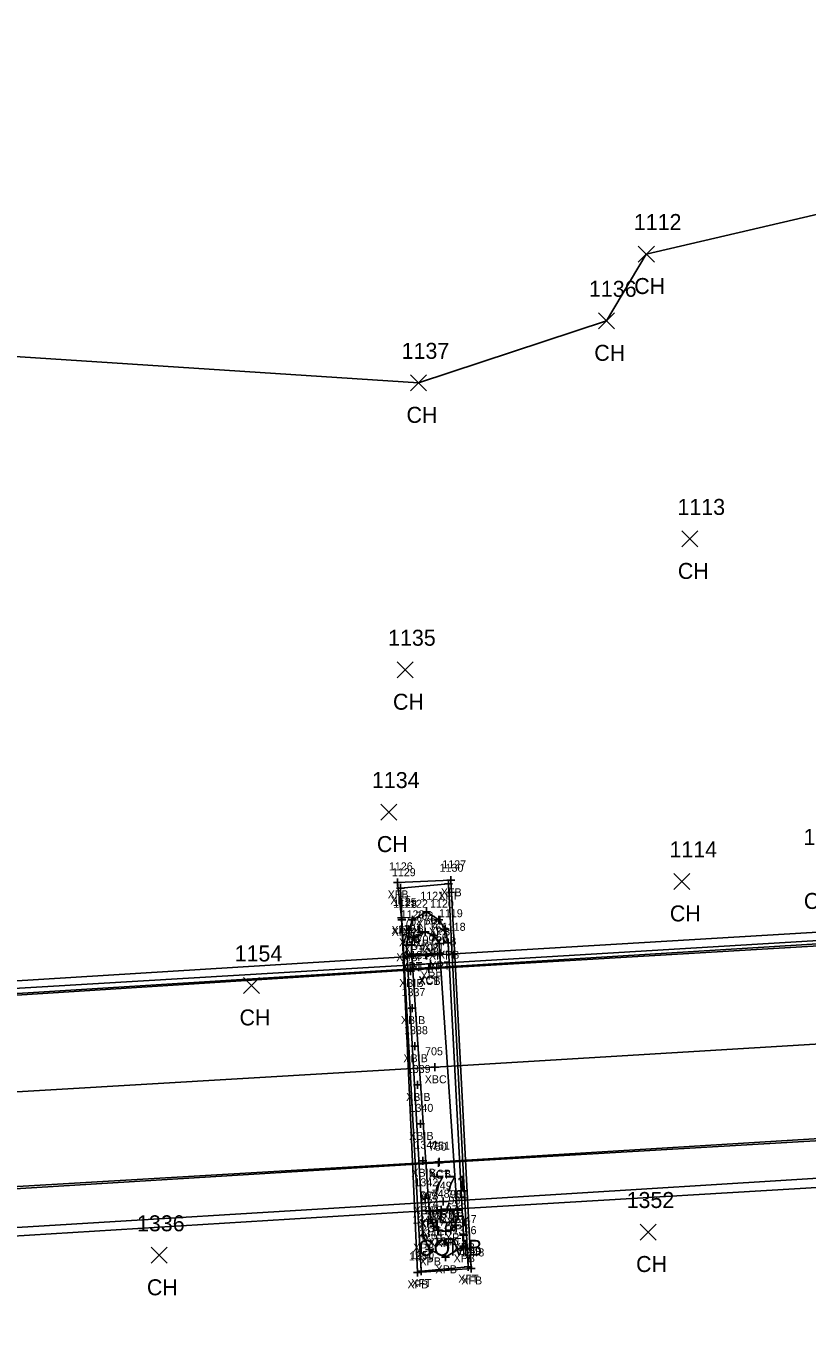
# Model space of a CAD drawing. Extents: x 1716490 to 1717645, y 888034 to 890004.
# Drawn here: x 1717066.5 to 1717164.1, y 888212.7 to 888374.8 of the extents above; entities that cross this region are included whole.
import ezdxf

# ---------------------------------------------------------------- set-up
doc = ezdxf.new("R2010")
doc.units = 0
for name, color, linetype in [('B_A', 7, 'Continuous'), ('B_I', 7, 'Continuous'), ('B_TIC', 7, 'Continuous'), ('BDC', 7, 'Continuous'), ('BELB', 7, 'Continuous'), ('BF', 7, 'Continuous'), ('BFT', 7, 'Continuous'), ('BR', 7, 'Continuous'), ('BSUBM', 7, 'Continuous'), ('L_A', 7, 'Continuous'), ('L_I', 7, 'Continuous'), ('L_TIC', 7, 'Continuous'), ('LSOGP', 7, 'Continuous'), ('U_A', 7, 'Continuous'), ('U_I', 7, 'Continuous'), ('UP', 7, 'Continuous')]:
    doc.layers.add(name, color=color, linetype=linetype)

msp = doc.modelspace()

# ---------------------------------------------------------------- linework, layer by layer
at = {"layer": 'B_TIC'}
for p, q in [((1717119.59, 888268.03), (1717119.67, 888268.03)), ((1717112.95, 888267.77), (1717113.03, 888267.77)), ((1717113.3, 888267.04), (1717113.38, 888267.04)), ((1717119.3, 888267.6), (1717119.37, 888267.6)), ((1717113.42, 888263.33), (1717113.5, 888263.33)), ((1717113.47, 888263.09), (1717113.54, 888263.09)), ((1717114.82, 888263.1), (1717114.9, 888263.1)), ((1717116.56, 888264.1), (1717116.64, 888264.1)), ((1717118.11, 888263.11), (1717118.19, 888263.11)), ((1717114.38, 888261.78), (1717114.46, 888261.78)), ((1717116.38, 888261.61), (1717116.45, 888261.61)), ((1717118.89, 888261.91), (1717118.97, 888261.91)), ((1717114.04, 888259.92), (1717114.12, 888259.92)), ((1717114.67, 888259.96), (1717114.75, 888259.96)), ((1717114.99, 888260.93), (1717115.07, 888260.93)), ((1717117.48, 888261.13), (1717117.56, 888261.13)), ((1717118.14, 888260.13), (1717118.21, 888260.13)), ((1717119.25, 888260.22), (1717119.33, 888260.22)), ((1717114.71, 888258.8), (1717114.78, 888258.8)), ((1717114.72, 888258.65), (1717114.8, 888258.65)), ((1717116.54, 888258.64), (1717116.62, 888258.64)), ((1717118.2, 888258.89), (1717118.28, 888258.89)), ((1717118.23, 888258.88), (1717118.31, 888258.88)), ((1717114.57, 888256.69), (1717114.65, 888256.69)), ((1717116.83, 888257.09), (1717116.91, 888257.09)), ((1717116.83, 888256.95), (1717116.91, 888256.95)), ((1717117.07, 888257.61), (1717117.14, 888257.61)), ((1717114.79, 888252.05), (1717114.86, 888252.05)), ((1717115.1, 888247.29), (1717115.18, 888247.29)), ((1717117.6, 888244.66), (1717117.68, 888244.66)), ((1717115.44, 888242.45), (1717115.52, 888242.45)), ((1717115.83, 888237.59), (1717115.9, 888237.59)), ((1717116.1, 888232.98), (1717116.18, 888232.98)), ((1717118.08, 888232.73), (1717118.15, 888232.73)), ((1717118.15, 888232.86), (1717118.23, 888232.86)), ((1717116.39, 888228.28), (1717116.46, 888228.28)), ((1717118.66, 888227.87), (1717118.73, 888227.87)), ((1717116.88, 888226.66), (1717116.96, 888226.66)), ((1717117, 888226.63), (1717117.08, 888226.63)), ((1717118.39, 888226.86), (1717118.47, 888226.86)), ((1717120.37, 888226.8), (1717120.44, 888226.8)), ((1717120.4, 888226.79), (1717120.48, 888226.79)), ((1717120.53, 888226.03), (1717120.61, 888226.03)), ((1717117.03, 888225.65), (1717117.1, 888225.65)), ((1717117.47, 888224.79), (1717117.54, 888224.79)), ((1717118.07, 888224.3), (1717118.15, 888224.3)), ((1717118.99, 888224.18), (1717119.07, 888224.18)), ((1717119.58, 888224.32), (1717119.66, 888224.32)), ((1717120.15, 888224.9), (1717120.22, 888224.9)), ((1717116.15, 888223.63), (1717116.22, 888223.63)), ((1717121.2, 888223.68), (1717121.28, 888223.68)), ((1717116.95, 888221.9), (1717117.03, 888221.9)), ((1717118.94, 888220.91), (1717119.02, 888220.91)), ((1717121.21, 888222.3), (1717121.28, 888222.3)), ((1717121.78, 888219.73), (1717121.85, 888219.73)), ((1717122.15, 888219.52), (1717122.23, 888219.52)), ((1717115.42, 888219.02), (1717115.5, 888219.02)), ((1717115.91, 888219.18), (1717115.99, 888219.18))]:
    msp.add_line(p, q, dxfattribs=at)
for points in [[(1717112.95, 888267.27), (1717112.95, 888268.27)], [(1717119.09, 888268.03), (1717120.09, 888268.03)], [(1717119.29, 888267.1), (1717119.29, 888268.1)], [(1717119.59, 888267.53), (1717119.59, 888268.53)], [(1717112.45, 888267.77), (1717113.45, 888267.77)], [(1717112.8, 888267.04), (1717113.8, 888267.04)], [(1717113.3, 888266.54), (1717113.3, 888267.54)], [(1717118.79, 888267.6), (1717119.79, 888267.6)], [(1717112.92, 888263.33), (1717113.92, 888263.33)], [(1717112.97, 888263.09), (1717113.97, 888263.09)], [(1717113.42, 888262.83), (1717113.42, 888263.83)], [(1717113.47, 888262.59), (1717113.47, 888263.59)], [(1717114.32, 888263.1), (1717115.32, 888263.1)], [(1717114.82, 888262.6), (1717114.82, 888263.6)], [(1717116.06, 888264.1), (1717117.06, 888264.1)], [(1717116.56, 888263.6), (1717116.56, 888264.6)], [(1717117.61, 888263.11), (1717118.61, 888263.11)], [(1717118.11, 888262.61), (1717118.11, 888263.61)], [(1717113.88, 888261.78), (1717114.88, 888261.78)], [(1717114.38, 888261.28), (1717114.38, 888262.28)], [(1717114.99, 888260.43), (1717114.99, 888261.43)], [(1717115.87, 888261.61), (1717116.87, 888261.61)], [(1717116.37, 888261.11), (1717116.37, 888262.11)], [(1717117.48, 888260.63), (1717117.48, 888261.63)], [(1717118.39, 888261.91), (1717119.39, 888261.91)], [(1717118.89, 888261.41), (1717118.89, 888262.41)], [(1717113.54, 888259.92), (1717114.54, 888259.92)], [(1717114.04, 888259.42), (1717114.04, 888260.42)], [(1717114.17, 888259.96), (1717115.17, 888259.96)], [(1717114.49, 888260.93), (1717115.49, 888260.93)], [(1717114.67, 888259.46), (1717114.67, 888260.46)], [(1717116.98, 888261.13), (1717117.98, 888261.13)], [(1717117.63, 888260.13), (1717118.63, 888260.13)], [(1717118.13, 888259.63), (1717118.13, 888260.63)], [(1717118.75, 888260.22), (1717119.75, 888260.22)], [(1717119.25, 888259.72), (1717119.25, 888260.72)], [(1717114.2, 888258.8), (1717115.2, 888258.8)], [(1717114.22, 888258.65), (1717115.22, 888258.65)], [(1717114.7, 888258.3), (1717114.7, 888259.3)], [(1717114.72, 888258.15), (1717114.72, 888259.15)], [(1717116.04, 888258.64), (1717117.04, 888258.64)], [(1717116.54, 888258.14), (1717116.54, 888259.14)], [(1717117.7, 888258.89), (1717118.7, 888258.89)], [(1717117.73, 888258.88), (1717118.73, 888258.88)], [(1717118.2, 888258.39), (1717118.2, 888259.39)], [(1717118.23, 888258.38), (1717118.23, 888259.38)], [(1717114.07, 888256.69), (1717115.07, 888256.69)], [(1717114.57, 888256.19), (1717114.57, 888257.19)], [(1717116.33, 888257.09), (1717117.33, 888257.09)], [(1717116.33, 888256.95), (1717117.33, 888256.95)], [(1717116.56, 888257.61), (1717117.56, 888257.61)], [(1717116.83, 888256.59), (1717116.83, 888257.59)], [(1717116.83, 888256.45), (1717116.83, 888257.45)], [(1717117.06, 888257.11), (1717117.06, 888258.11)], [(1717114.28, 888252.05), (1717115.28, 888252.05)], [(1717114.78, 888251.55), (1717114.78, 888252.55)], [(1717114.6, 888247.29), (1717115.6, 888247.29)], [(1717115.1, 888246.79), (1717115.1, 888247.79)], [(1717117.6, 888244.16), (1717117.6, 888245.16)], [(1717117.1, 888244.66), (1717118.1, 888244.66)], [(1717114.94, 888242.45), (1717115.94, 888242.45)], [(1717115.44, 888241.95), (1717115.44, 888242.95)], [(1717115.32, 888237.59), (1717116.32, 888237.59)], [(1717115.82, 888237.09), (1717115.82, 888238.09)], [(1717115.6, 888232.98), (1717116.6, 888232.98)], [(1717116.1, 888232.48), (1717116.1, 888233.48)], [(1717117.57, 888232.73), (1717118.57, 888232.73)], [(1717117.65, 888232.86), (1717118.65, 888232.86)], [(1717118.07, 888232.23), (1717118.07, 888233.23)], [(1717118.15, 888232.36), (1717118.15, 888233.36)], [(1717115.88, 888228.28), (1717116.88, 888228.28)], [(1717116.38, 888227.78), (1717116.38, 888228.78)], [(1717118.15, 888227.87), (1717119.15, 888227.87)], [(1717118.39, 888226.36), (1717118.39, 888227.36)], [(1717118.65, 888227.37), (1717118.65, 888228.37)], [(1717116.38, 888226.66), (1717117.38, 888226.66)], [(1717116.5, 888226.63), (1717117.5, 888226.63)], [(1717116.88, 888226.16), (1717116.88, 888227.16)], [(1717117, 888226.13), (1717117, 888227.13)], [(1717117.03, 888225.15), (1717117.03, 888226.15)], [(1717117.89, 888226.86), (1717118.89, 888226.86)], [(1717119.87, 888226.8), (1717120.87, 888226.8)], [(1717119.9, 888226.79), (1717120.9, 888226.79)], [(1717120.03, 888226.03), (1717121.03, 888226.03)], [(1717120.37, 888226.3), (1717120.37, 888227.3)], [(1717120.4, 888226.29), (1717120.4, 888227.29)], [(1717120.53, 888225.53), (1717120.53, 888226.53)], [(1717116.14, 888223.13), (1717116.14, 888224.13)], [(1717116.53, 888225.65), (1717117.53, 888225.65)], [(1717116.96, 888224.79), (1717117.96, 888224.79)], [(1717117.46, 888224.29), (1717117.46, 888225.29)], [(1717117.57, 888224.3), (1717118.57, 888224.3)], [(1717118.07, 888223.8), (1717118.07, 888224.8)], [(1717118.49, 888224.18), (1717119.49, 888224.18)], [(1717118.99, 888223.68), (1717118.99, 888224.68)], [(1717119.08, 888224.32), (1717120.08, 888224.32)], [(1717119.58, 888223.82), (1717119.58, 888224.82)], [(1717119.64, 888224.9), (1717120.64, 888224.9)], [(1717120.14, 888224.4), (1717120.14, 888225.4)], [(1717121.2, 888223.18), (1717121.2, 888224.18)], [(1717115.64, 888223.63), (1717116.64, 888223.63)], [(1717120.7, 888223.68), (1717121.7, 888223.68)], [(1717121.2, 888221.8), (1717121.2, 888222.8)], [(1717116.45, 888221.9), (1717117.45, 888221.9)], [(1717116.95, 888221.4), (1717116.95, 888222.4)], [(1717118.44, 888220.91), (1717119.44, 888220.91)], [(1717118.94, 888220.41), (1717118.94, 888221.41)], [(1717120.7, 888222.3), (1717121.7, 888222.3)], [(1717115.42, 888218.52), (1717115.42, 888219.52)], [(1717115.91, 888218.68), (1717115.91, 888219.68)], [(1717121.28, 888219.73), (1717122.28, 888219.73)], [(1717121.65, 888219.52), (1717122.65, 888219.52)], [(1717121.78, 888219.23), (1717121.78, 888220.23)], [(1717122.15, 888219.02), (1717122.15, 888220.02)], [(1717114.92, 888219.02), (1717115.92, 888219.02)], [(1717115.41, 888219.18), (1717116.41, 888219.18)]]:
    msp.add_lwpolyline(points, dxfattribs=at)
at = {"layer": 'BDC'}
for points in [[(1717176.59, 888262.23), (1717176.88, 888260.81), (1717116.83, 888257.09), (1717056.7, 888253.34), (1716997.03, 888249.86), (1716937, 888246.31), (1716877.5, 888242.93), (1716877.3, 888244.49)], [(1717176.98, 888262.02), (1717176.87, 888260.51), (1717116.83, 888256.95), (1717056.83, 888253.15), (1716997, 888249.66), (1716937.06, 888246.1), (1716877.42, 888242.56)], [(1716878.98, 888212.69), (1716878.75, 888218.61), (1716938.22, 888221.98), (1716998.22, 888225.49), (1717058.32, 888229.07), (1717118.07, 888232.73), (1717177.98, 888236.21), (1717178.1, 888235.65), (1717178.63, 888230.44)], [(1716878.76, 888218.78), (1716938.25, 888222.24), (1716997.85, 888225.86), (1717058.28, 888229.34), (1717118.15, 888232.86), (1717177.91, 888236.5)]]:
    msp.add_lwpolyline(points, dxfattribs=at)
at = {"layer": 'BELB'}
msp.add_lwpolyline([(1717176.82, 888248.24), (1717117.6, 888244.66), (1717057.58, 888241.13), (1716997.66, 888237.53), (1716937.87, 888233.85), (1716878.26, 888230.51)], dxfattribs=at)
at = {"layer": 'BF'}
for points in [[(1717176.59, 888262.23), (1717116.54, 888258.64), (1717056.61, 888254.94), (1716996.92, 888251.43), (1716937.1, 888247.95), (1716877.3, 888244.49)], [(1716878.98, 888212.69), (1716938.93, 888216.1), (1716998.54, 888219.73), (1717058.79, 888223.18), (1717118.39, 888226.86), (1717178.63, 888230.44)]]:
    msp.add_lwpolyline(points, dxfattribs=at)
at = {"layer": 'BFT'}
for points in [[(1717113.42, 888263.33), (1717112.95, 888267.77), (1717119.59, 888268.03), (1717122.15, 888219.52), (1717115.42, 888219.02)], [(1717113.47, 888263.09), (1717113.3, 888267.04), (1717119.29, 888267.6), (1717121.78, 888219.73), (1717115.91, 888219.18)], [(1717115.42, 888219.02), (1717113.42, 888263.33)], [(1717115.91, 888219.18), (1717113.47, 888263.09)]]:
    msp.add_lwpolyline(points, dxfattribs=at)
at = {"layer": 'BR'}
for points in [[(1717176, 888261.98), (1717175.88, 888261.14), (1717117.06, 888257.61), (1717056.56, 888254), (1716997.02, 888250.41), (1716936.97, 888246.78), (1716878.14, 888243.39), (1716877.96, 888244.41)], [(1716879.62, 888212.9), (1716879.68, 888213.78), (1716938.7, 888217.13), (1716998.52, 888220.76), (1717058.5, 888224.21), (1717118.65, 888227.87), (1717177.58, 888231.53), (1717177.86, 888230.64)]]:
    msp.add_lwpolyline(points, dxfattribs=at)
at = {"layer": 'BSUBM'}
for points in [[(1717119.25, 888260.22), (1717118.89, 888261.91), (1717118.11, 888263.11), (1717116.56, 888264.1), (1717114.82, 888263.1), (1717114.38, 888261.78), (1717114.04, 888259.92), (1717116.14, 888223.63), (1717116.95, 888221.9), (1717118.94, 888220.91), (1717121.2, 888222.3), (1717121.2, 888223.68)], [(1717114.7, 888258.8), (1717114.67, 888259.96), (1717114.99, 888260.93), (1717116.37, 888261.61), (1717117.48, 888261.13), (1717118.13, 888260.13), (1717118.2, 888258.89)], [(1717121.2, 888223.68), (1717119.25, 888260.22)], [(1717118.2, 888258.89), (1717114.7, 888258.8)], [(1717118.23, 888258.88), (1717114.72, 888258.65), (1717116.88, 888226.66), (1717120.37, 888226.8)], [(1717120.37, 888226.8), (1717118.23, 888258.88)], [(1717117, 888226.63), (1717117.03, 888225.65), (1717117.46, 888224.79), (1717118.07, 888224.3), (1717118.99, 888224.18), (1717119.58, 888224.32), (1717120.14, 888224.9), (1717120.53, 888226.03), (1717120.4, 888226.79)], [(1717120.4, 888226.79), (1717117, 888226.63)]]:
    msp.add_lwpolyline(points, dxfattribs=at)
at = {"layer": 'L_TIC'}
for points in [[(1717143.02, 888345.31), (1717145.02, 888347.31)], [(1717145.02, 888345.31), (1717143.02, 888347.31)], [(1717138.03, 888336.96), (1717140.03, 888338.96)], [(1717140.03, 888336.96), (1717138.03, 888338.96)], [(1717114.57, 888329.21), (1717116.57, 888331.21)], [(1717116.57, 888329.21), (1717114.57, 888331.21)], [(1717148.47, 888309.7), (1717150.47, 888311.7)], [(1717150.47, 888309.7), (1717148.47, 888311.7)], [(1717112.89, 888293.35), (1717114.89, 888295.35)], [(1717114.89, 888293.35), (1717112.89, 888295.35)], [(1717110.87, 888275.56), (1717112.87, 888277.56)], [(1717112.87, 888275.56), (1717110.87, 888277.56)], [(1717147.47, 888266.89), (1717149.47, 888268.89)], [(1717149.47, 888266.89), (1717147.47, 888268.89)], [(1717093.71, 888253.89), (1717095.71, 888255.89)], [(1717095.71, 888253.89), (1717093.71, 888255.89)], [(1717143.25, 888223.07), (1717145.25, 888225.07)], [(1717145.25, 888223.07), (1717143.25, 888225.07)], [(1717082.14, 888220.16), (1717084.14, 888222.16)], [(1717084.14, 888220.16), (1717082.14, 888222.16)]]:
    msp.add_lwpolyline(points, dxfattribs=at)
at = {"layer": 'LSOGP'}
msp.add_lwpolyline([(1717397.44, 888368.91), (1717347.56, 888372.82), (1717313.58, 888368.41), (1717284.61, 888374.82), (1717226.58, 888372.74), (1717200.46, 888359.46), (1717144.02, 888346.31), (1717139.03, 888337.96), (1717115.57, 888330.22), (1717057.48, 888334.02)], dxfattribs=at)
at = {"layer": 'UP'}
for p, q in [((1717119.37, 888227.77), (1717119.12, 888226.93)), ((1717118.29, 888225.27), (1717118.29, 888226.93)), ((1717118.29, 888226.93), (1717119.95, 888226.93)), ((1717119.12, 888226.1), (1717119.12, 888226.1)), ((1717119.95, 888226.93), (1717119.95, 888225.27)), ((1717119.95, 888225.27), (1717118.29, 888225.27)), ((1717118.87, 888224.43), (1717119.12, 888225.27))]:
    msp.add_line(p, q, dxfattribs=at)
msp.add_circle((1717119.12, 888226.1), 0.833, dxfattribs=at)

# ---------------------------------------------------------------- texts
at = {"layer": 'B_A'}
for s, p in [('XFB', (1717111.71, 888265.77)), ('XFT', (1717118.04, 888265.6)), ('XFB', (1717118.35, 888266.03)), ('XFT', (1717112.04, 888265.04)), ('XPB', (1717115.3, 888262.1)), ('XFB', (1717112.18, 888261.33)), ('XFT', (1717112.21, 888261.09)), ('XPB', (1717113.56, 888261.1)), ('XPB', (1717116.85, 888261.11)), ('XPB', (1717113.12, 888259.78)), ('XPT', (1717113.71, 888258.93)), ('XPT', (1717115.09, 888259.61)), ('XPT', (1717116.2, 888259.13)), ('XPB', (1717117.63, 888259.91)), ('XPB', (1717112.78, 888257.92)), ('XPT', (1717113.39, 888257.96)), ('XPT', (1717116.86, 888258.13)), ('XPB', (1717117.99, 888258.22)), ('XPT', (1717113.42, 888256.8)), ('XPT', (1717113.44, 888256.65)), ('XFAT', (1717114.79, 888256.64)), ('XRF', (1717115.82, 888255.61)), ('XPT', (1717116.92, 888256.89)), ('XPT', (1717116.95, 888256.88)), ('XBIB', (1717113.14, 888254.69)), ('XCT', (1717115.55, 888255.09)), ('XCB', (1717115.56, 888254.95)), ('XBIB', (1717113.35, 888250.05)), ('XBIB', (1717113.67, 888245.29)), ('XBC', (1717116.33, 888242.66)), ('XBIB', (1717114.01, 888240.45)), ('XBIB', (1717114.39, 888235.59)), ('XBIB', (1717114.67, 888230.98)), ('XCT', (1717116.79, 888230.73)), ('XCB', (1717116.88, 888230.86)), ('XBIB', (1717114.95, 888226.28)), ('XFAT', (1717116.64, 888224.86)), ('XRF', (1717117.41, 888225.87)), ('XPT', (1717119.09, 888224.8)), ('XPT', (1717119.12, 888224.79)), ('XPT', (1717115.6, 888224.66)), ('XPT', (1717115.72, 888224.63)), ('XPT', (1717115.75, 888223.65)), ('XPT', (1717119.25, 888224.03)), ('XPB', (1717114.88, 888221.63)), ('XPT', (1717116.18, 888222.79)), ('XPT', (1717116.79, 888222.3)), ('XPT', (1717117.71, 888222.18)), ('XPT', (1717118.3, 888222.32)), ('XPT', (1717118.86, 888222.9)), ('XPB', (1717119.94, 888221.68)), ('XPB', (1717115.68, 888219.9)), ('XPB', (1717119.94, 888220.3)), ('XPB', (1717117.68, 888218.91)), ('XFB', (1717114.18, 888217.02)), ('XFT', (1717114.65, 888217.18)), ('XFT', (1717120.52, 888217.73)), ('XFB', (1717120.91, 888217.52))]:
    msp.add_text(s, height=1, dxfattribs=at).set_placement(p)
at = {"layer": 'B_I'}
for s, p in [('1126', (1717111.86, 888269.27)), ('1129', (1717112.23, 888268.54)), ('1130', (1717118.19, 888269.1)), ('1127', (1717118.53, 888269.53)), ('1121', (1717115.78, 888265.6)), ('1125', (1717112.35, 888264.83)), ('1128', (1717112.4, 888264.59)), ('1122', (1717113.76, 888264.6)), ('1120', (1717117, 888264.61)), ('1123', (1717113.32, 888263.28)), ('762', (1717113.78, 888262.43)), ('763', (1717115.17, 888263.11)), ('764', (1717116.27, 888262.63)), ('1119', (1717118.11, 888263.41)), ('1124', (1717112.98, 888261.42)), ('761', (1717113.75, 888261.46)), ('765', (1717116.93, 888261.63)), ('766', (1717116.97, 888260.39)), ('767', (1717117.02, 888260.38)), ('1118', (1717118.47, 888261.72)), ('760', (1717113.46, 888260.3)), ('768', (1717113.51, 888260.15)), ('709', (1717115.31, 888260.14)), ('708', (1717115.84, 888259.11)), ('1131', (1717113.79, 888258.19)), ('706', (1717115.58, 888258.45)), ('707', (1717115.61, 888258.59)), ('1337', (1717113.44, 888253.55)), ('1338', (1717113.75, 888248.79)), ('705', (1717116.38, 888246.16)), ('1339', (1717114.09, 888243.95)), ('1340', (1717114.43, 888239.09)), ('1341', (1717115.04, 888234.48)), ('750', (1717116.85, 888234.23)), ('751', (1717117.25, 888234.36)), ('1342', (1717115.04, 888229.78)), ('769', (1717115.67, 888228.16)), ('973', (1717115.82, 888228.13)), ('748', (1717117.21, 888228.36)), ('749', (1717117.47, 888229.37)), ('770', (1717119.14, 888228.3)), ('981', (1717119.5, 888228.29)), ('974', (1717115.84, 888227.15)), ('979', (1717118.96, 888226.4)), ('980', (1717119.3, 888227.53)), ('1343', (1717114.8, 888225.13)), ('975', (1717116.28, 888226.29)), ('976', (1717116.86, 888225.8)), ('977', (1717117.81, 888225.68)), ('978', (1717118.4, 888225.82)), ('1347', (1717119.85, 888225.18)), ('1344', (1717115.6, 888223.4)), ('1346', (1717119.83, 888223.8)), ('1345', (1717117.59, 888222.41)), ('1351', (1717114.36, 888220.52)), ('1350', (1717114.52, 888220.68)), ('1349', (1717120.43, 888221.23)), ('1348', (1717120.8, 888221.02))]:
    msp.add_text(s, height=1, dxfattribs=at).set_placement(p)
at = {"layer": 'L_A'}
for p in [(1717142.51, 888341.31), (1717137.52, 888332.96), (1717114.06, 888325.21), (1717147.96, 888305.7), (1717112.37, 888289.35), (1717110.36, 888271.56), (1717163.7, 888264.45), (1717146.96, 888262.89), (1717093.2, 888249.89), (1717142.74, 888219.07), (1717081.63, 888216.16)]:
    msp.add_text('CH', height=2, dxfattribs=at).set_placement(p)
at = {"layer": 'L_I'}
for s, p in [('1112', (1717142.46, 888349.31)), ('1136', (1717136.85, 888340.96)), ('1137', (1717113.45, 888333.21)), ('1113', (1717147.91, 888313.7)), ('1135', (1717111.76, 888297.35)), ('1134', (1717109.74, 888279.56)), ('1117', (1717163.65, 888272.45)), ('1114', (1717146.91, 888270.89)), ('1154', (1717092.59, 888257.89)), ('1352', (1717141.56, 888227.07)), ('1336', (1717080.39, 888224.16))]:
    msp.add_text(s, height=2, dxfattribs=at).set_placement(p)
at = {"layer": 'U_A'}
msp.add_text('COMB', height=2, dxfattribs=at).set_placement((1717115.51, 888221.1))
at = {"layer": 'U_I'}
msp.add_text('771', height=2, dxfattribs=at).set_placement((1717117.32, 888229.1))

doc.saveas('drawing.dxf')
